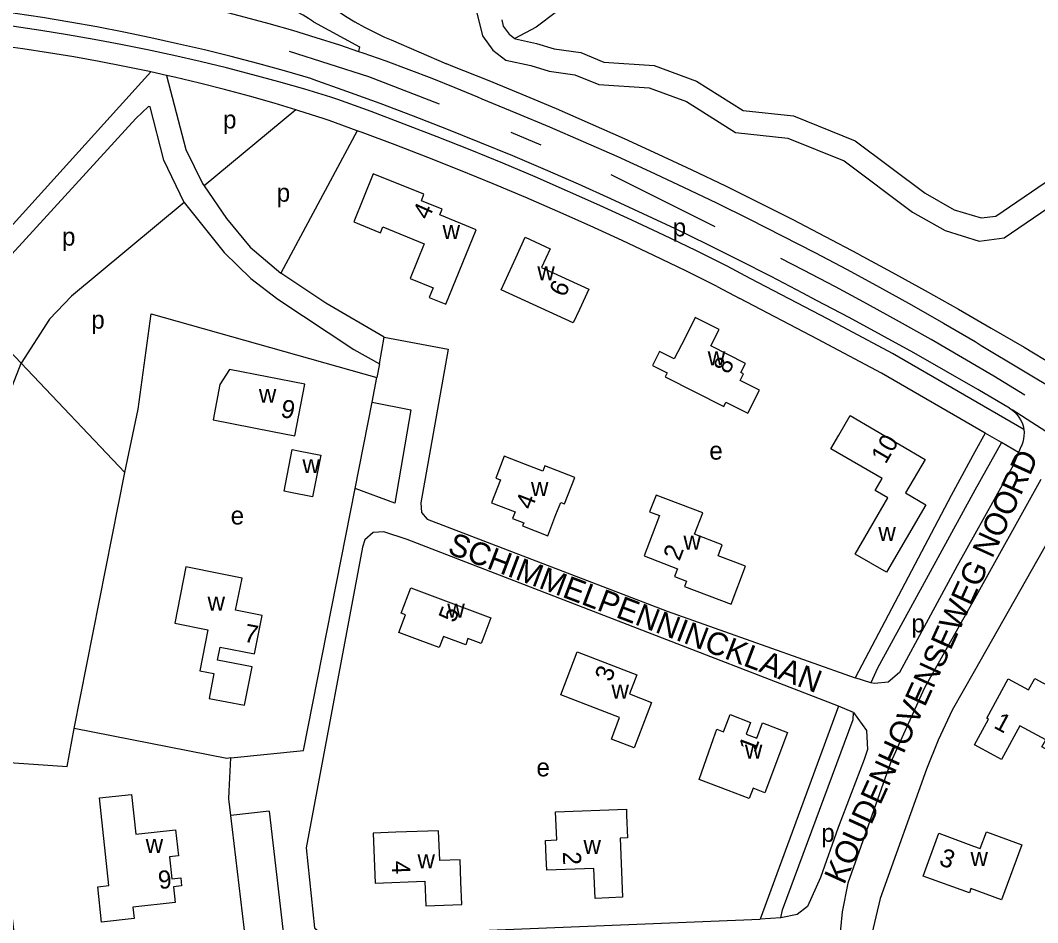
# Model space of a CAD drawing. Extents: x 162427 to 165104, y 384242 to 386287.
# Drawn here: x 163093 to 163317.6, y 385195.4 to 385394.6 of the extents above; entities that cross this region are included whole.
import ezdxf

# ---------------------------------------------------------------- set-up
doc = ezdxf.new("R2010")
doc.units = 0
for name, color, linetype in [('BLT_Basislijn', 7, 'Continuous'), ('BLT_Bebouwing', 7, 'Continuous'), ('BLT_Centroide', 7, 'Continuous'), ('BLT_Huisnummer', 7, 'Continuous'), ('BLT_Straatnaam', 7, 'Continuous'), ('BLT_Vlakafsluiter', 7, 'Continuous')]:
    doc.layers.add(name, color=color, linetype=linetype)

msp = doc.modelspace()

# ---------------------------------------------------------------- linework, layer by layer
at = {"layer": 'BLT_Basislijn'}
for p, q in [((163174.82, 385390.3), (163187.06, 385385.02)), ((163080.36, 385337.47), (163121.81, 385383.22)), ((163125.27, 385382.45), (163121.81, 385383.22)), ((163153.77, 385374.88), (163133.56, 385358.08)), ((163167.35, 385370.26), (163150.52, 385338.79)), ((163201.28, 385369.95), (163207.87, 385367.12)), ((163246.38, 385349.03), (163223.41, 385360.52)), ((163254.12, 385337.64), (163249.07, 385340.33)), ((163246.84, 385335.86), (163251.81, 385333.2)), ((163080.8, 385331.81), (163093.14, 385318.96)), ((163172.27, 385318.8), (163173.32, 385324.67)), ((163305.15, 385322.83), (163338.76, 385302.67)), ((163093.14, 385318.96), (163116.06, 385294.81)), ((163172.27, 385318.8), (163171.71, 385315.77)), ((163170.64, 385310.31), (163171.71, 385315.77)), ((163166.89, 385291.26), (163170.64, 385310.31)), ((163309.59, 385301.39), (163306.03, 385303.45)), ((163313.4, 385299.19), (163309.59, 385301.39)), ((163313.98, 385300.57), (163313.4, 385299.19)), ((163313.4, 385299.19), (163312.25, 385296.49)), ((163104.85, 385238.23), (163116.06, 385294.81)), ((163280.79, 385248.35), (163277.27, 385249.45)), ((163273.62, 385243.23), (163256.32, 385196.16)), ((163276.94, 385241.79), (163273.62, 385243.23)), ((163139.07, 385224.42), (163139.45, 385231.76)), ((163147.91, 385220.01), (163139.43, 385219.07)), ((163147.91, 385220.01), (163151.18, 385192.06)), ((163142.78, 385191.21), (163139.43, 385219.07)), ((163260.9, 385196.49), (163256.32, 385196.16))]:
    msp.add_line(p, q, dxfattribs=at)
for points in [[(163327.95, 385508.07), (163328.41, 385506.28), (163327.94, 385505.14), (163211.35, 385396.5), (163206.89, 385393.15), (163202.14, 385390.64)], [(163202.14, 385390.64), (163202.31, 385390.51), (163206.97, 385389.51), (163210.81, 385388.31), (163216.7, 385387.49), (163221.83, 385385.39), (163232.9, 385384.69), (163242.29, 385381.22), (163252.6, 385374.69), (163263.65, 385373.52), (163277.32, 385368.01), (163292.74, 385356.49), (163299.16, 385352.81), (163305.13, 385351), (163308.38, 385351.41), (163386.46, 385404.75), (163389.6, 385405.58), (163392.11, 385405.3)], [(163121.43, 385400.25), (163126.74, 385399.14), (163132.04, 385397.95), (163137.32, 385396.69), (163142.58, 385395.35), (163147.82, 385393.93), (163153.04, 385392.43), (163158.24, 385390.85), (163163.41, 385389.2), (163167.65, 385387.78)], [(163193.46, 385397.49), (163194.98, 385391.17), (163197.32, 385388.01), (163200.19, 385385.85), (163205.7, 385384.67), (163209.71, 385383.42), (163215.38, 385382.63), (163220.7, 385380.45), (163231.85, 385379.75), (163240.06, 385376.71), (163250.91, 385369.84), (163262.43, 385368.63), (163274.85, 385363.62), (163289.99, 385352.3), (163297.17, 385348.19), (163304.7, 385345.9), (163310.21, 385346.61), (163388.56, 385400.14), (163389.16, 385400.29)], [(163157.11, 385381.75), (163151.27, 385383.45), (163145.4, 385385.07), (163139.52, 385386.61), (163133.62, 385388.08), (163127.7, 385389.46), (163121.76, 385390.77), (163115.81, 385392), (163109.84, 385393.16), (163103.86, 385394.23), (163097.86, 385395.23), (163091.85, 385396.14), (163085.82, 385396.98), (163079.79, 385397.74), (163073.75, 385398.41), (163067.7, 385399.01), (163064.08, 385399.33)], [(163157.72, 385394.27), (163156.58, 385395.05), (163155.39, 385395.76), (163154.17, 385396.41), (163152.91, 385396.98), (163151.62, 385397.48), (163150.31, 385397.91), (163148.97, 385398.26), (163148.51, 385398.36)], [(163160.66, 385398.3), (163162.68, 385396.91), (163164.74, 385395.58), (163166.84, 385394.31), (163168.98, 385393.12), (163171.16, 385391.99), (163173.37, 385390.94), (163174.82, 385390.3)], [(163161.53, 385377.68), (163155.81, 385379.41), (163150.06, 385381.05), (163144.29, 385382.62), (163138.5, 385384.11), (163132.69, 385385.53), (163126.87, 385386.86), (163121.02, 385388.12), (163115.16, 385389.3), (163109.29, 385390.4), (163103.4, 385391.43), (163097.49, 385392.37), (163091.58, 385393.23), (163085.65, 385394.02), (163082.4, 385394.42)], [(163157.72, 385394.27), (163167.85, 385388.79), (163167.65, 385387.78)], [(163199.25, 385394.77), (163199.6, 385393.33), (163200.9, 385391.57), (163202.14, 385390.64)], [(163121.81, 385383.22), (163121.48, 385383.3), (163115.93, 385384.46), (163110.35, 385385.55), (163104.76, 385386.55), (163099.16, 385387.48), (163093.54, 385388.33), (163087.92, 385389.1), (163083.15, 385389.69)], [(163152.32, 385387.85), (163169.83, 385382.2), (163185.46, 385376.17)], [(163167.65, 385387.78), (163168.56, 385387.48), (163173.68, 385385.68), (163178.78, 385383.8), (163183.85, 385381.85), (163188.88, 385379.82), (163193.89, 385377.72), (163194.88, 385377.3)], [(163241.3, 385361.56), (163233.87, 385365.03), (163226.38, 385368.46), (163218.87, 385371.8), (163211.32, 385375.08), (163203.74, 385378.28), (163196.14, 385381.41), (163188.5, 385384.46), (163187.06, 385385.02)], [(163153.77, 385374.88), (163149, 385376.31), (163143.54, 385377.86), (163138.05, 385379.33), (163132.55, 385380.73), (163127.03, 385382.05), (163125.27, 385382.45)], [(163125.27, 385382.45), (163129.53, 385366.14), (163133.19, 385358.63), (163133.56, 385358.08)], [(163265.72, 385334.38), (163258.75, 385338.04), (163251.74, 385341.62), (163244.7, 385345.13), (163237.62, 385348.57), (163230.5, 385351.94), (163223.36, 385355.23), (163216.18, 385358.45), (163208.96, 385361.6), (163201.72, 385364.68), (163194.44, 385367.68), (163187.14, 385370.61), (163179.8, 385373.46), (163172.44, 385376.24), (163165.05, 385378.94), (163157.63, 385381.57), (163157.11, 385381.75)], [(163249.07, 385340.33), (163242.1, 385343.79), (163235.08, 385347.19), (163228.02, 385350.51), (163220.93, 385353.76), (163213.81, 385356.94), (163206.66, 385360.05), (163199.47, 385363.08), (163192.26, 385366.04), (163185.01, 385368.92), (163177.73, 385371.73), (163170.43, 385374.47), (163163.1, 385377.12), (163161.53, 385377.68)], [(163194.88, 385377.3), (163202.37, 385374.23), (163209.84, 385371.09), (163217.27, 385367.88), (163224.67, 385364.6), (163232.04, 385361.24), (163239.38, 385357.81), (163246.68, 385354.3), (163253.95, 385350.73), (163261.18, 385347.08), (163268.37, 385343.36), (163275.53, 385339.58), (163282.65, 385335.72), (163289.73, 385331.79), (163296.77, 385327.79), (163303.77, 385323.72), (163305.15, 385322.83)], [(163129.12, 385354.39), (163124.66, 385363.72), (163121.61, 385375.54), (163121.26, 385375.58), (163118.48, 385372.93), (163080.8, 385331.81)], [(163159.86, 385372.97), (163154.44, 385374.68), (163153.77, 385374.88)], [(163167.35, 385370.26), (163161.13, 385372.52), (163159.86, 385372.97)], [(163246.84, 385335.86), (163239.88, 385339.31), (163232.88, 385342.7), (163225.85, 385346.01), (163218.78, 385349.25), (163211.68, 385352.42), (163204.55, 385355.51), (163197.39, 385358.53), (163190.19, 385361.48), (163182.97, 385364.35), (163175.72, 385367.15), (163168.44, 385369.87), (163167.35, 385370.26)], [(163278.02, 385343), (163270.76, 385346.85), (163263.45, 385350.63), (163256.11, 385354.34), (163248.73, 385357.98), (163241.3, 385361.56)], [(163133.56, 385358.08), (163138.5, 385350.84), (163143.68, 385344.58), (163150.52, 385338.79)], [(163129.12, 385354.39), (163104.25, 385333.72), (163099.38, 385328.61), (163093.14, 385318.96)], [(163129.12, 385354.39), (163137.96, 385343.39), (163143.84, 385337.64), (163149.79, 385333.03), (163166.62, 385321.98), (163172.27, 385318.8)], [(163314.75, 385311.9), (163307.89, 385316.05), (163300.99, 385320.13), (163294.05, 385324.14), (163287.07, 385328.08), (163280.05, 385331.95), (163272.99, 385335.75), (163265.89, 385339.48), (163260.89, 385342.05)], [(163278.02, 385343), (163285.42, 385339.02), (163292.77, 385334.98), (163300.09, 385330.87), (163307.36, 385326.68), (163314.6, 385322.43), (163321.19, 385318.48)], [(163173.32, 385324.67), (163160.4, 385332.2), (163150.52, 385338.79)], [(163314.52, 385304.32), (163285.54, 385321.08), (163271.33, 385328.66), (163254.12, 385337.64)], [(163311.36, 385308.99), (163304.37, 385313.13), (163297.33, 385317.2), (163290.26, 385321.21), (163283.14, 385325.14), (163275.99, 385329), (163268.8, 385332.79), (163265.72, 385334.38)], [(163306.03, 385303.45), (163283.11, 385316.71), (163268.99, 385324.24), (163251.81, 385333.2)], [(163116.06, 385294.81), (163118.97, 385308.75), (163121.83, 385329.79), (163171.71, 385315.77)], [(163173.32, 385324.67), (163187.46, 385322.01), (163181.37, 385288.09), (163181.53, 385285.99), (163182.8, 385284.47), (163235.82, 385264.18), (163277.27, 385249.45)], [(163050.17, 385099.92), (163057.2, 385114.94), (163058.93, 385119.41), (163060.54, 385129.27), (163060.68, 385134.28), (163056.7, 385183.49), (163052.96, 385210.26), (163053.62, 385218.8), (163055.24, 385224.74), (163057.81, 385232.41), (163074.99, 385264.65), (163090.72, 385312.68), (163093.14, 385318.96)], [(163170.64, 385310.31), (163179.22, 385308.61), (163175.65, 385288.03), (163166.89, 385291.26)], [(163311.36, 385308.99), (163311.97, 385308.59)], [(163311.97, 385308.59), (163312.52, 385308.13), (163313.02, 385307.61), (163313.46, 385307.03), (163313.84, 385306.41), (163314.14, 385305.75), (163314.37, 385305.07), (163314.52, 385304.32)], [(163306.03, 385303.45), (163303.76, 385299.33), (163298.51, 385289.73), (163277.27, 385249.45)], [(163314.52, 385304.32), (163314.59, 385303.64), (163314.58, 385302.91), (163314.49, 385302.2), (163314.33, 385301.49), (163314.09, 385300.81), (163313.98, 385300.57)], [(163309.59, 385301.39), (163303.73, 385290.9), (163282.22, 385251.62), (163280.79, 385248.35)], [(163312.25, 385296.49), (163303.69, 385281.17), (163299.8, 385274.21), (163287.11, 385250.6), (163284.56, 385248.51), (163281.6, 385248.17), (163280.79, 385248.35)], [(163318.27, 385293.27), (163303.64, 385266.9), (163292.63, 385247.23), (163285.11, 385230.66), (163275.67, 385204.1), (163274.41, 385197.77), (163273.42, 385187.12), (163273.67, 385179.73), (163279.17, 385144.44), (163279.67, 385143.09), (163280.53, 385142.07), (163282.1, 385141.12), (163284.19, 385141.07), (163287.03, 385141.75)], [(163139.45, 385231.76), (163155.48, 385233.39), (163166.89, 385291.26)], [(163326.37, 385291.14), (163303.58, 385250.87), (163298.75, 385242.34), (163295.64, 385235.71), (163293.07, 385229.31), (163282.82, 385200.76), (163280.63, 385191.41), (163280.79, 385182.02), (163287.03, 385141.75)], [(163273.62, 385243.23), (163178.35, 385280.02), (163173.26, 385281.72), (163170.87, 385281.56), (163169.03, 385279.95), (163168.49, 385278.27), (163156.09, 385211.91), (163157.93, 385194.24), (163160.22, 385192.27), (163256.32, 385196.16)], [(163260.9, 385196.49), (163261.27, 385198.2), (163276.84, 385240.26), (163276.94, 385241.79)], [(163276.94, 385241.79), (163279.79, 385237.84), (163279.99, 385233.61), (163279.32, 385231.43), (163273.54, 385216.44), (163269.62, 385205.37), (163266.76, 385198.98), (163264.51, 385197.19), (163260.9, 385196.49)], [(163135.11, 385146.8), (163097.33, 385142.31), (163087.26, 385230.97), (163103.3, 385229.91), (163104.85, 385238.23)], [(163139.45, 385231.76), (163138.54, 385231.67), (163104.85, 385238.23)], [(163139.43, 385219.07), (163138.99, 385222.74), (163139.07, 385224.42)]]:
    msp.add_lwpolyline(points, dxfattribs=at)
at = {"layer": 'BLT_Bebouwing'}
for points in [[(163183.23, 385333.44), (163186.94, 385331.98), (163193.62, 385348.38), (163185.58, 385351.65), (163186.12, 385352.97), (163181.57, 385354.8), (163182.04, 385356.23), (163170.91, 385360.7), (163166.57, 385350.11), (163172.47, 385347.73), (163173, 385349.02), (163182.17, 385345.27), (163179.05, 385337.64), (163184.1, 385335.57), (163183.23, 385333.44)], [(163218.48, 385335.28), (163216.41, 385330.78), (163215.04, 385327.81), (163199.11, 385335.13), (163202.35, 385342.17), (163204.44, 385346.72), (163209.93, 385344.2), (163208.04, 385340.08), (163218.48, 385335.28)], [(163248.27, 385309.36), (163248.75, 385310.32), (163253.59, 385307.87), (163256.17, 385312.96), (163251.93, 385315.11), (163252.66, 385316.55), (163252.06, 385316.86), (163253.09, 385318.89), (163245.46, 385322.75), (163247.28, 385326.35), (163242, 385329.02), (163239.74, 385324.56), (163237.37, 385319.88), (163234.13, 385321.52), (163232.57, 385318.43), (163235.81, 385316.79), (163235.35, 385315.89), (163248.27, 385309.36)], [(163148.68, 385303.84), (163153.59, 385302.88), (163155.8, 385314.27), (163139.14, 385317.52), (163137.03, 385314.22), (163135.51, 385306.41), (163148.68, 385303.84)], [(163277.31, 385276.79), (163284.55, 385289.2), (163281.74, 385290.84), (163283.25, 385293.43), (163271.93, 385300.03), (163273.68, 385303.02), (163276.2, 385307.34), (163292.74, 385297.68), (163288.42, 385290.28), (163292.91, 385287.66), (163284.22, 385272.76), (163277.31, 385276.79)], [(163154.4, 385299.61), (163159.31, 385298.65), (163157.51, 385289.43), (163152.6, 385290.39), (163151.19, 385290.66), (163152.99, 385299.88), (163154.4, 385299.61)], [(163211.24, 385285.5), (163212.28, 385288.2), (163213.15, 385287.86), (163215.4, 385293.72), (163208.78, 385296.26), (163208.33, 385295.09), (163204.48, 385296.56), (163199.81, 385298.36), (163197.96, 385293.54), (163198.97, 385293.15), (163197.03, 385288.1), (163202.23, 385286.1), (163201.65, 385284.6), (163204.11, 385283.65), (163203.85, 385282.98), (163209.45, 385280.83), (163211.24, 385285.5)], [(163253.11, 385274.08), (163247.04, 385276.39), (163247.97, 385278.85), (163241.85, 385281.18), (163243.64, 385285.87), (163233.33, 385289.8), (163231.92, 385286.1), (163234.08, 385285.27), (163232.46, 385281.03), (163230.68, 385276.36), (163238.07, 385273.54), (163237.4, 385271.79), (163240.08, 385270.77), (163239.65, 385269.65), (163249.93, 385265.73), (163253.11, 385274.08)], [(163129.51, 385273.93), (163127.05, 385261.5)], [(163146.33, 385263.21), (163140.51, 385264.36), (163141.92, 385271.49), (163137.14, 385272.39), (163129.51, 385273.93)], [(163195.09, 385257.99), (163194.73, 385257.03), (163191.81, 385258.13), (163191.3, 385256.77), (163186.39, 385258.61), (163185.46, 385256.13), (163181.24, 385257.72), (163176.56, 385259.48), (163178.02, 385263.37), (163177.07, 385263.73), (163179.17, 385269.32), (163196.85, 385262.67), (163195.09, 385257.99)], [(163144.67, 385254.76), (163146.33, 385263.21)], [(163127.05, 385261.5), (163134.36, 385260.06), (163132.57, 385250.98), (163135.71, 385250.42), (163134.66, 385244.92), (163142.46, 385243.43)], [(163144.12, 385251.89), (163136.5, 385253.38), (163137.07, 385256.24), (163144.67, 385254.76)], [(163142.46, 385243.43), (163144.12, 385251.89)], [(163321.34, 385246.95), (163330.66, 385241.91), (163324.66, 385230.82), (163322.34, 385232.08), (163322.74, 385232.82), (163321.15, 385233.68), (163320.78, 385232.99), (163318.55, 385234.2), (163319.4, 385235.78), (163313.67, 385238.89), (163309.63, 385231.43), (163308.03, 385232.3), (163303.63, 385234.68), (163306.71, 385240.35), (163306.38, 385240.53), (163311.11, 385249.26), (163315.59, 385246.83), (163316.95, 385249.33), (163321.34, 385246.95)], [(163249.24, 385224.61), (163242.83, 385227.04), (163246, 385236.03), (163246.79, 385238.11), (163248.24, 385237.56), (163249.67, 385241.34), (163254.19, 385239.62), (163253.21, 385237.03), (163255.56, 385236.14), (163256.82, 385239.49), (163262.37, 385237.39), (163257.33, 385224.08), (163254.75, 385225.06), (163253.91, 385222.84), (163249.24, 385224.61)], [(163211.16, 385219.85), (163226.79, 385220.45), (163226.83, 385219.53), (163226.84, 385219.1), (163227.04, 385214.1), (163225.44, 385214.04), (163225.93, 385200.99), (163219.86, 385200.76), (163219.61, 385207.37), (163209.21, 385206.97), (163209.1, 385209.77), (163208.96, 385213.57), (163211.4, 385213.66), (163211.16, 385219.85)], [(163190.25, 385204.4), (163190.07, 385209.28), (163185.56, 385209.12), (163185.33, 385215.67), (163175.9, 385215.34), (163170.91, 385215.16), (163171.3, 385204.15), (163182.31, 385204.54), (163182.5, 385199.12), (163190.42, 385199.41), (163190.25, 385204.4)], [(163303.44, 385212.32), (163304.93, 385211.78), (163306.27, 385215.44), (163314.07, 385212.59), (163309.63, 385200.44), (163302.87, 385202.91), (163302.53, 385201.98), (163292.32, 385205.69), (163295.77, 385215.12), (163303.44, 385212.32)]]:
    msp.add_lwpolyline(points, dxfattribs=at)
for points in [[(163215.95, 385255.18), (163229.11, 385250.14), (163227.48, 385245.89), (163232.32, 385244.04), (163228.47, 385234), (163223.47, 385235.92), (163225.3, 385240.71), (163212.31, 385245.68)], [(163117.52, 385223.68), (163118.47, 385214.91), (163127.24, 385215.86), (163127.86, 385210.16), (163125.92, 385209.95), (163126.44, 385205.09), (163128.39, 385205.31), (163128.58, 385203.54), (163126.78, 385203.33), (163127.17, 385199.81), (163117.83, 385198.8), (163118.1, 385196.3), (163110.9, 385195.54), (163110.08, 385203.33), (163112.52, 385203.59), (163110.46, 385222.93)]]:
    msp.add_lwpolyline(points, close=True, dxfattribs=at)
at = {"layer": 'BLT_Vlakafsluiter'}
msp.add_line((163327.79, 385298.4), (163311.97, 385308.59), dxfattribs=at)

# ---------------------------------------------------------------- texts
at = {"layer": 'BLT_Centroide'}
for s, p in [('p', (163137.72, 385370.75)), ('p', (163149.57, 385354.58)), ('p', (163237.01, 385346.93)), ('p', (163102.16, 385344.88)), ('w', (163186.19, 385346.34)), ('w', (163207.12, 385337.25)), ('p', (163108.63, 385326.55)), ('w', (163244.75, 385318.44)), ('w', (163145.63, 385310.19)), ('e', (163245.1, 385297.63)), ('w', (163155.25, 385294.66)), ('w', (163205.71, 385289.59)), ('e', (163139.41, 385283.31)), ('w', (163282.42, 385279.69)), ('w', (163239.39, 385277.75)), ('w', (163134.3, 385264.31)), ('w', (163187.24, 385262.72)), ('p', (163289.72, 385259.5)), ('w', (163223.49, 385244.88)), ('w', (163252.95, 385231.64)), ('e', (163206.93, 385227.69)), ('p', (163269.82, 385213.23)), ('w', (163120.64, 385210.81)), ('w', (163217.31, 385210.59)), ('w', (163302.76, 385207.94)), ('w', (163180.66, 385207.41))]:
    msp.add_text(s, height=4, dxfattribs=at).set_placement(p)
at = {"layer": 'BLT_Huisnummer'}
for s, rotation, p in [('4', 65.7543, (163183.07, 385350.39)), ('6', 65.3119, (163213.19, 385333.33)), ('8', 63.1531, (163249.36, 385316.32)), ('9', 348.9756, (163150.26, 385307.09)), ('10', 59.7402, (163284.03, 385296.49)), ('4', 68.9861, (163205.91, 385286.37)), ('2', 69.1483, (163238.5, 385275.09)), ('5', 69.3903, (163188.92, 385261.45)), ('7', 349.4184, (163142.15, 385257.49)), ('3', 69.0586, (163223.39, 385248.39)), ('1', 331.5797, (163307.68, 385238.53)), ('1', 69.2455, (163255.19, 385232.74)), ('2', 272.1892, (163212.74, 385211.02)), ('3', 339.974, (163295.61, 385208.22)), ('4', 272.0445, (163174.98, 385208.99)), ('9', 6.5055, (163123.62, 385202.78))]:
    msp.add_text(s, height=4, rotation=rotation, dxfattribs=at).set_placement(p)
at = {"layer": 'BLT_Straatnaam'}
for s, height, rotation, p in [('KOUDENHOVENSEWEG NOORD', 4.9999, 65.5643, (163274.84, 385203.59)), ('SCHIMMELPENNINCKLAAN', 5, 339.2348, (163187.06, 385277))]:
    msp.add_text(s, height=height, rotation=rotation, dxfattribs=at).set_placement(p)

doc.saveas('drawing.dxf')
